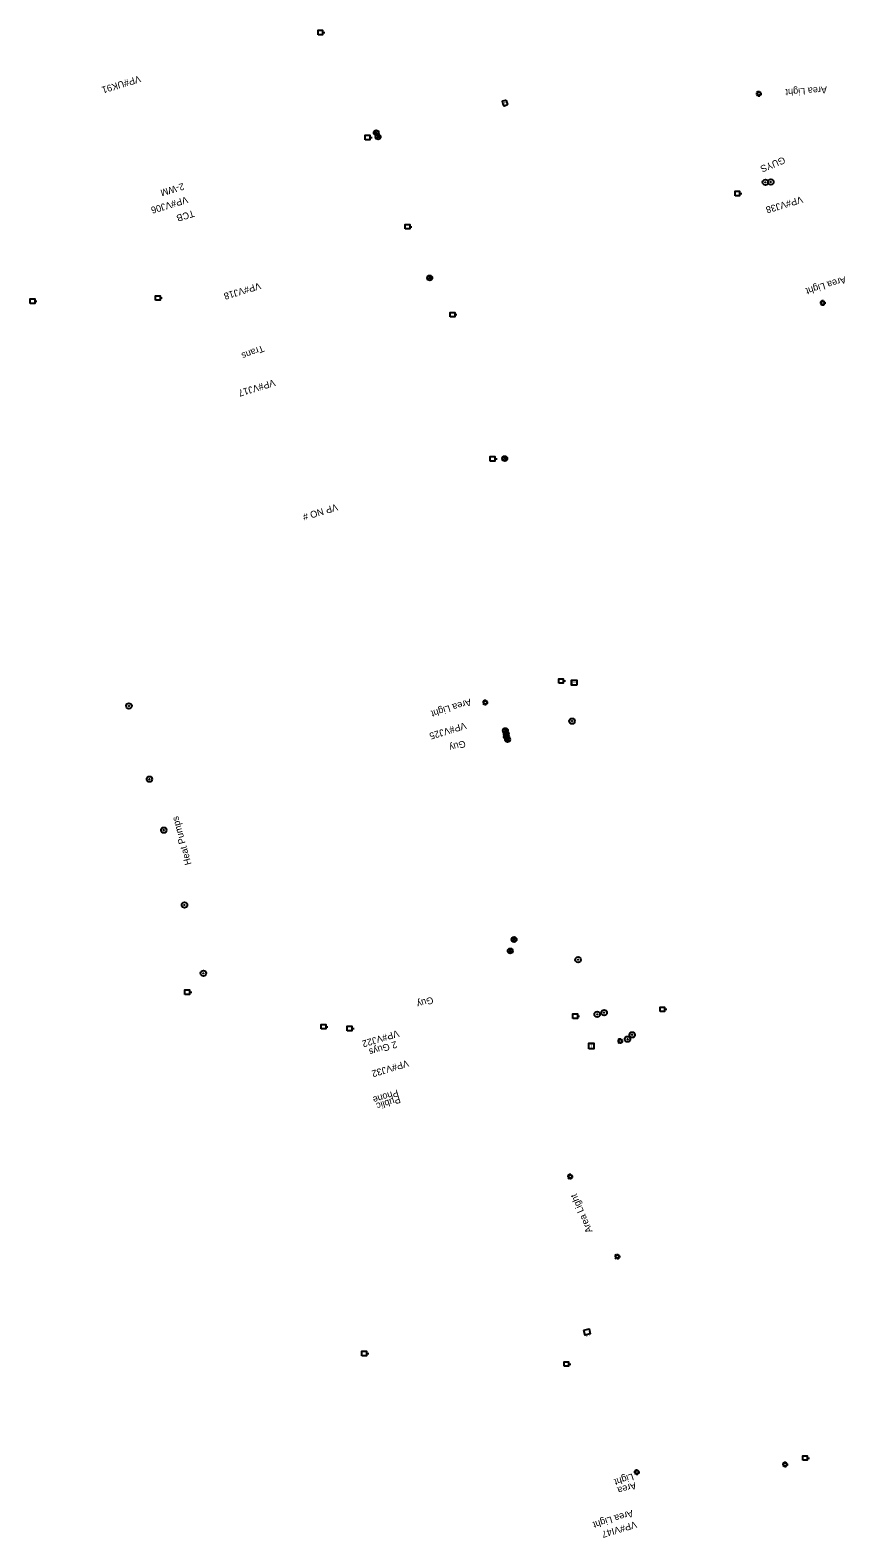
# Model space of a CAD drawing. Extents: x 3872070 to 3879223, y 293944 to 310567.
# Drawn here: x 3874265 to 3874624, y 306618 to 307282 of the extents above; entities that cross this region are included whole.
import ezdxf

# ---------------------------------------------------------------- set-up
doc = ezdxf.new("R2010")
doc.units = 0
for name, color, linetype in [('Level 34', 7, 'Continuous'), ('Level 35', 7, 'Continuous'), ('Level 37', 7, 'Continuous'), ('Level 39', 7, 'Continuous'), ('Level 4', 7, 'Continuous'), ('Level 5', 7, 'Continuous'), ('Level 7', 7, 'Continuous'), ('Level 9', 7, 'Continuous')]:
    doc.layers.add(name, color=color, linetype=linetype)

msp = doc.modelspace()

# ---------------------------------------------------------------- linework, layer by layer
at = {"layer": 'Level 4'}
for p, q in [((3874393.86, 307281.2), (3874394.86, 307281.2)), ((3874586.01, 307254.92), (3874586.01, 307255.5)), ((3874585.28, 307254.2), (3874584.71, 307254.2)), ((3874585.5, 307254.71), (3874585.09, 307255.12)), ((3874585.09, 307253.28), (3874585.5, 307253.68)), ((3874586.01, 307253.47), (3874586.01, 307252.9)), ((3874586.52, 307254.71), (3874586.93, 307255.12)), ((3874586.93, 307253.28), (3874586.52, 307253.68)), ((3874586.73, 307254.2), (3874587.31, 307254.2)), ((3874414.67, 307234.89), (3874415.67, 307234.89)), ((3874577.54, 307210.25), (3874578.54, 307210.25)), ((3874432.24, 307195.64), (3874433.24, 307195.64)), ((3874267.1, 307162.85), (3874268.1, 307162.85)), ((3874322.29, 307164.24), (3874323.29, 307164.24)), ((3874613.64, 307162.58), (3874613.23, 307162.98)), ((3874614.15, 307162.79), (3874614.15, 307163.36)), ((3874614.66, 307162.58), (3874615.07, 307162.98)), ((3874452.05, 307156.91), (3874453.05, 307156.91)), ((3874613.42, 307162.06), (3874612.85, 307162.06)), ((3874613.23, 307161.14), (3874613.64, 307161.55)), ((3874614.15, 307161.34), (3874614.15, 307160.76)), ((3874615.07, 307161.14), (3874614.66, 307161.55)), ((3874614.87, 307162.06), (3874615.45, 307162.06)), ((3874469.7, 307093.4), (3874470.7, 307093.4)), ((3874499.85, 306995.58), (3874500.85, 306995.58)), ((3874464.82, 306986.11), (3874464.25, 306986.11)), ((3874465.04, 306986.63), (3874464.63, 306987.03)), ((3874464.63, 306985.2), (3874465.04, 306985.6)), ((3874465.55, 306986.84), (3874465.55, 306987.41)), ((3874465.55, 306985.39), (3874465.55, 306984.82)), ((3874466.06, 306986.63), (3874466.47, 306987.03)), ((3874466.47, 306985.2), (3874466.06, 306985.6)), ((3874466.27, 306986.11), (3874466.85, 306986.11)), ((3874335.27, 306858.53), (3874336.27, 306858.53)), ((3874544.52, 306850.98), (3874545.52, 306850.98)), ((3874506.07, 306847.99), (3874507.07, 306847.99)), ((3874395.26, 306843.3), (3874396.26, 306843.3)), ((3874406.73, 306842.51), (3874407.73, 306842.51)), ((3874524.27, 306837), (3874523.7, 306837)), ((3874524.48, 306837.51), (3874524.08, 306837.92)), ((3874525, 306837.72), (3874525, 306838.3)), ((3874525.51, 306837.51), (3874525.92, 306837.92)), ((3874525.72, 306837), (3874526.3, 306837)), ((3874524.08, 306836.08), (3874524.48, 306836.49)), ((3874525, 306836.27), (3874525, 306835.7)), ((3874525.92, 306836.08), (3874525.51, 306836.49)), ((3874502.2, 306777.3), (3874501.63, 306777.3)), ((3874502.42, 306777.81), (3874502.01, 306778.22)), ((3874502.93, 306778.02), (3874502.93, 306778.6)), ((3874503.44, 306777.81), (3874503.85, 306778.22)), ((3874503.65, 306777.3), (3874504.23, 306777.3)), ((3874502.01, 306776.38), (3874502.42, 306776.78)), ((3874502.93, 306776.57), (3874502.93, 306776)), ((3874503.85, 306776.38), (3874503.44, 306776.78)), ((3874522.98, 306742.05), (3874522.41, 306742.05)), ((3874523.2, 306742.56), (3874522.79, 306742.97)), ((3874522.79, 306741.13), (3874523.2, 306741.54)), ((3874523.71, 306742.77), (3874523.71, 306743.35)), ((3874523.71, 306741.32), (3874523.71, 306740.75)), ((3874524.22, 306742.56), (3874524.63, 306742.97)), ((3874524.63, 306741.13), (3874524.22, 306741.54)), ((3874524.43, 306742.05), (3874525.01, 306742.05)), ((3874413.22, 306699.4), (3874414.22, 306699.4)), ((3874502.23, 306694.75), (3874503.23, 306694.75)), ((3874597.06, 306651.02), (3874596.65, 306651.43)), ((3874597.57, 306651.23), (3874597.57, 306651.81)), ((3874598.09, 306651.02), (3874598.49, 306651.43)), ((3874607.33, 306653.34), (3874608.33, 306653.34)), ((3874531.56, 306647.14), (3874530.98, 306647.14)), ((3874531.77, 306647.65), (3874531.36, 306648.06)), ((3874531.36, 306646.22), (3874531.77, 306646.63)), ((3874532.28, 306647.87), (3874532.28, 306648.44)), ((3874532.28, 306646.42), (3874532.28, 306645.84)), ((3874532.79, 306647.65), (3874533.2, 306648.06)), ((3874533.2, 306646.22), (3874532.79, 306646.63)), ((3874533.01, 306647.14), (3874533.58, 306647.14)), ((3874596.85, 306650.51), (3874596.27, 306650.51)), ((3874596.65, 306649.59), (3874597.06, 306650)), ((3874597.57, 306649.78), (3874597.57, 306649.21)), ((3874598.49, 306649.59), (3874598.09, 306650)), ((3874598.3, 306650.51), (3874598.87, 306650.51))]:
    msp.add_line(p, q, dxfattribs=at)
for points in [[(3874391.86, 307280.2), (3874391.86, 307282.2), (3874393.86, 307282.2), (3874393.86, 307280.2)], [(3874412.67, 307233.89), (3874412.67, 307235.89), (3874414.67, 307235.89), (3874414.67, 307233.89)], [(3874575.54, 307209.25), (3874575.54, 307211.25), (3874577.54, 307211.25), (3874577.54, 307209.25)], [(3874430.24, 307194.64), (3874430.24, 307196.64), (3874432.24, 307196.64), (3874432.24, 307194.64)], [(3874265.1, 307161.85), (3874265.1, 307163.85), (3874267.1, 307163.85), (3874267.1, 307161.85)], [(3874320.29, 307163.24), (3874320.29, 307165.24), (3874322.29, 307165.24), (3874322.29, 307163.24)], [(3874450.05, 307155.91), (3874450.05, 307157.91), (3874452.05, 307157.91), (3874452.05, 307155.91)], [(3874467.7, 307092.4), (3874467.7, 307094.4), (3874469.7, 307094.4), (3874469.7, 307092.4)], [(3874497.85, 306994.58), (3874497.85, 306996.58), (3874499.85, 306996.58), (3874499.85, 306994.58)], [(3874333.27, 306857.53), (3874333.27, 306859.53), (3874335.27, 306859.53), (3874335.27, 306857.53)], [(3874542.52, 306849.98), (3874542.52, 306851.98), (3874544.52, 306851.98), (3874544.52, 306849.98)], [(3874393.26, 306842.3), (3874393.26, 306844.3), (3874395.26, 306844.3), (3874395.26, 306842.3)], [(3874504.07, 306846.99), (3874504.07, 306848.99), (3874506.07, 306848.99), (3874506.07, 306846.99)], [(3874404.73, 306841.51), (3874404.73, 306843.51), (3874406.73, 306843.51), (3874406.73, 306841.51)], [(3874508.91, 306709.59), (3874511.23, 306710.19), (3874511.78, 306708.07), (3874509.45, 306707.47)], [(3874411.22, 306698.4), (3874411.22, 306700.4), (3874413.22, 306700.4), (3874413.22, 306698.4)], [(3874500.23, 306693.75), (3874500.23, 306695.75), (3874502.23, 306695.75), (3874502.23, 306693.75)], [(3874605.33, 306652.34), (3874605.33, 306654.34), (3874607.33, 306654.34), (3874607.33, 306652.34)]]:
    msp.add_lwpolyline(points, close=True, dxfattribs=at)
for centre, radius in [((3874586.01, 307254.2), 0.725), ((3874588.88, 307215.19), 1.22), ((3874591.27, 307215.33), 1.22), ((3874591.27, 307215.33), 0.0992), ((3874588.88, 307215.19), 0.0992), ((3874588.88, 307215.19), 0.0483), ((3874591.27, 307215.33), 0.0483), ((3874614.15, 307162.06), 0.725), ((3874308.59, 306984.57), 1.22), ((3874308.59, 306984.57), 0.0992), ((3874308.59, 306984.57), 0.0483), ((3874465.55, 306986.11), 0.725), ((3874503.76, 306977.88), 1.22), ((3874503.76, 306977.88), 0.0992), ((3874503.76, 306977.88), 0.0483), ((3874317.63, 306952.32), 1.22), ((3874317.63, 306952.32), 0.0992), ((3874317.63, 306952.32), 0.0483), ((3874323.94, 306929.89), 1.22), ((3874323.94, 306929.89), 0.0992), ((3874323.94, 306929.89), 0.0483), ((3874333.05, 306896.88), 1.22), ((3874333.05, 306896.88), 0.0992), ((3874333.05, 306896.88), 0.0483), ((3874506.39, 306872.82), 1.22), ((3874506.39, 306872.82), 0.0992), ((3874506.39, 306872.82), 0.0483), ((3874341.4, 306866.82), 1.22), ((3874341.4, 306866.82), 0.0992), ((3874341.4, 306866.82), 0.0483), ((3874517.87, 306849.52), 1.22), ((3874514.82, 306848.77), 1.22), ((3874514.82, 306848.77), 0.0992), ((3874514.82, 306848.77), 0.0483), ((3874517.87, 306849.52), 0.0992), ((3874517.87, 306849.52), 0.0483), ((3874525, 306837), 0.725), ((3874528.17, 306837.8), 1.22), ((3874528.17, 306837.8), 0.0992), ((3874528.17, 306837.8), 0.0483), ((3874530.2, 306839.75), 1.22), ((3874530.2, 306839.75), 0.0992), ((3874530.2, 306839.75), 0.0483), ((3874502.93, 306777.3), 0.725), ((3874523.71, 306742.05), 0.725), ((3874597.57, 306650.51), 0.725), ((3874532.28, 306647.14), 0.725)]:
    msp.add_circle(centre, radius, dxfattribs=at)
at = {"layer": 'Level 5'}
for p, q in [((3874416.74, 307237.8), (3874417.53, 307237)), ((3874416.74, 307236.21), (3874417.53, 307237)), ((3874417.5, 307235.97), (3874418.29, 307235.17)), ((3874418.33, 307237.8), (3874417.53, 307237)), ((3874418.33, 307236.21), (3874417.53, 307237)), ((3874419.09, 307235.97), (3874418.29, 307235.17)), ((3874417.5, 307234.38), (3874418.29, 307235.17)), ((3874419.09, 307234.38), (3874418.29, 307235.17)), ((3874440.29, 307173.88), (3874441.09, 307173.08)), ((3874440.29, 307172.29), (3874441.09, 307173.08)), ((3874441.88, 307173.88), (3874441.09, 307173.08)), ((3874441.88, 307172.29), (3874441.09, 307173.08)), ((3874473.31, 307094.31), (3874474.11, 307093.52)), ((3874473.31, 307092.72), (3874474.11, 307093.52)), ((3874474.9, 307094.31), (3874474.11, 307093.52)), ((3874474.9, 307092.72), (3874474.11, 307093.52)), ((3874473.61, 306974.5), (3874474.41, 306973.71)), ((3874473.61, 306972.91), (3874474.41, 306973.71)), ((3874473.97, 306973), (3874474.77, 306972.21)), ((3874473.97, 306971.41), (3874474.77, 306972.21)), ((3874474.09, 306971.74), (3874474.89, 306970.95)), ((3874474.09, 306970.15), (3874474.89, 306970.95)), ((3874475.2, 306974.5), (3874474.41, 306973.71)), ((3874475.2, 306972.91), (3874474.41, 306973.71)), ((3874474.57, 306970.54), (3874475.37, 306969.75)), ((3874474.57, 306968.95), (3874475.37, 306969.75)), ((3874475.56, 306973), (3874474.77, 306972.21)), ((3874475.56, 306971.41), (3874474.77, 306972.21)), ((3874475.68, 306971.74), (3874474.89, 306970.95)), ((3874475.68, 306970.15), (3874474.89, 306970.95)), ((3874476.16, 306970.54), (3874475.37, 306969.75)), ((3874476.16, 306968.95), (3874475.37, 306969.75)), ((3874475.74, 306877.49), (3874476.54, 306876.7)), ((3874477.33, 306877.49), (3874476.54, 306876.7)), ((3874477.42, 306882.53), (3874478.21, 306881.73)), ((3874477.42, 306880.94), (3874478.21, 306881.73)), ((3874479.01, 306882.53), (3874478.21, 306881.73)), ((3874479.01, 306880.94), (3874478.21, 306881.73)), ((3874475.74, 306875.9), (3874476.54, 306876.7)), ((3874477.33, 306875.9), (3874476.54, 306876.7))]:
    msp.add_line(p, q, dxfattribs=at)
for centre in [(3874417.53, 307237), (3874418.29, 307235.17), (3874441.09, 307173.08), (3874474.11, 307093.52), (3874474.41, 306973.7), (3874474.77, 306972.21), (3874474.89, 306970.95), (3874475.37, 306969.75), (3874476.53, 306876.7), (3874478.21, 306881.73)]:
    msp.add_circle(centre, 1.12, dxfattribs=at)
at = {"layer": 'Level 7'}
for points in [[(3874505.85, 306993.73), (3874503.46, 306993.73), (3874503.46, 306995.92), (3874505.85, 306995.92)], [(3874511.17, 306833.61), (3874511.17, 306836.01), (3874513.35, 306836.01), (3874513.35, 306833.61)]]:
    msp.add_lwpolyline(points, close=True, dxfattribs=at)
at = {"layer": 'Level 9'}
msp.add_lwpolyline([(3874473.57, 307248.97), (3874473.08, 307250.81), (3874473.26, 307251.12), (3874474.45, 307251.43), (3874474.75, 307251.25), (3874475.24, 307249.41), (3874475.06, 307249.1), (3874473.87, 307248.79)], close=True, dxfattribs=at)

# ---------------------------------------------------------------- texts
at = {"layer": 'Level 34'}
for s, rotation, p in [('VP#UK91', 196.9281, (3874313.22, 307262.28)), ('Area Light', 183.74415, (3874615.92, 307257.45)), ('GUYS', 202.07567, (3874596.9, 307226.55)), ('VP#VJ38', 196.9281, (3874604.81, 307209.16)), ('VP#VJ06', 196.9281, (3874334.02, 307209.05)), ('VP#VJ18', 196.9281, (3874366.12, 307171.15)), ('Area Light', 197.24972, (3874623.88, 307173.89)), ('Trans', 201.13993, (3874367.43, 307143.56)), ('VP#VJ17', 196.9281, (3874372.48, 307128.48)), ('VP NO #', 196.9281, (3874399.99, 307073.66)), ('Area Light', 197.24972, (3874458.82, 306987.81)), ('VP#VJ25', 196.9281, (3874456.62, 306977.45)), ('Guy', 196.63046, (3874456.36, 306969.5)), ('Heat Pumps', 105.54501, (3874336.17, 306914.96)), ('Guy', 196.63046, (3874442.16, 306856.6)), ('VP#VJ22', 196.9281, (3874427, 306841.89)), ('2 Guys', 196.63046, (3874426.13, 306837.03)), ('VP#VJ32', 196.9281, (3874431.24, 306828.73)), ('Area Light', 112.95602, (3874512.77, 306753.21)), ('Light', 197.24972, (3874530.34, 306646.62)), ('Area', 197.24972, (3874531.53, 306642.8)), ('Area Light', 197.24972, (3874530.13, 306630.55)), ('VP#VI47', 196.9281, (3874531.67, 306625.62))]:
    msp.add_text(s, height=3, rotation=rotation, dxfattribs=at).set_placement(p)
at = {"layer": 'Level 35'}
msp.add_text('2-WM', height=3, rotation=196.9281, dxfattribs=at).set_placement((3874332.45, 307214.96))
at = {"layer": 'Level 37'}
for s, p in [('Phone', (3874426.78, 306815.67)), ('Public', (3874427.66, 306812.78))]:
    msp.add_text(s, height=3, rotation=196.9281, dxfattribs=at).set_placement(p)
at = {"layer": 'Level 39'}
msp.add_text('TCB', height=3, rotation=196.9281, dxfattribs=at).set_placement((3874336.92, 307203))
at = {"layer": 'Level 4'}
msp.add_text('E', height=1.41, rotation=284.5, dxfattribs=at).set_placement((3874509.79, 306707.84))
at = {"layer": 'Level 7'}
msp.add_text('T', height=1.41, rotation=90, dxfattribs=at).set_placement((3874505.41, 306994.26))
msp.add_text('T', height=1.41, dxfattribs=at).set_placement((3874511.68, 306834.03))
at = {"layer": 'Level 9'}
msp.add_text('H', height=1.41, rotation=14.66511, dxfattribs=at).set_placement((3874473.89, 307249.31))

doc.saveas('drawing.dxf')
